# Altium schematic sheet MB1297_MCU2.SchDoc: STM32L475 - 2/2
size A4; DocumentNumber: MB1297; Revision: C; SheetNumber: 3; SheetTotal: 11
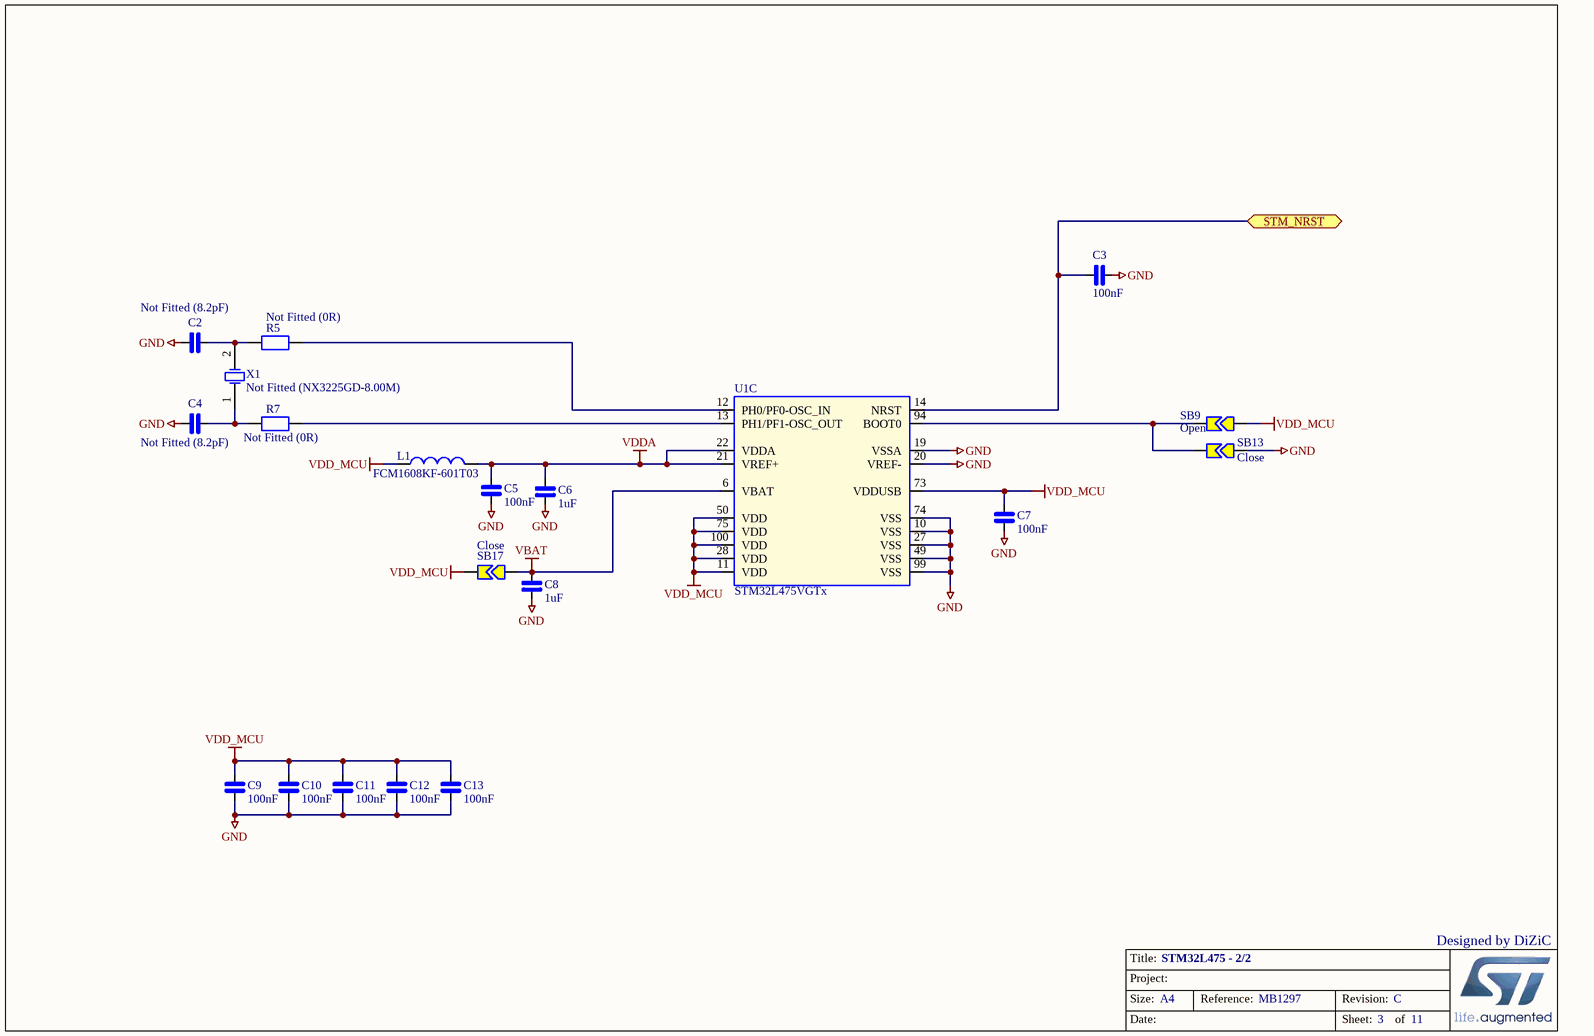
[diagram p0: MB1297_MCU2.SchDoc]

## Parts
C2  Not Fitted (8.2pF)  [0402_CAP_NPOL]
C3  100nF  [0402_CAP_NPOL]
C4  Not Fitted (8.2pF)  [0402_CAP_NPOL]
C5  100nF  [0402_CAP_NPOL]
C6  1uF  [0402_CAP_NPOL]
C7  100nF  [0402_CAP_NPOL]
C8  1uF  [0402_CAP_NPOL]
C9  100nF  [0402_CAP_NPOL]
C10  100nF  [0402_CAP_NPOL]
C11  100nF  [0402_CAP_NPOL]
C12  100nF  [0402_CAP_NPOL]
C13  100nF  [0402_CAP_NPOL]
L1  FCM1608KF-601T03  [0603L]
R5  Not Fitted (0R)  [0402_RES]
R7  Not Fitted (0R)  [0402_RES]
SB9  Open  [SB]
SB13  Close  [SB]
SB17  Close  [SB]
U1  STM32L475VGTx  [LQFP100 14x14x1.6]  (part C of 3)
X1  Not Fitted (NX3225GD-8.00M)  [CRY_NX3225GD_2P]

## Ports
STM_NRST

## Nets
GND: C2.2 C3.1 C4.2 C5.2 C6.1 C7.2 C8.1 C9.2 C10.2 C11.2 C12.2 C13.2 SB13.1 U1.10(VSS) U1.19(VSSA) U1.20(VREF-) U1.27(VSS) U1.49(VSS) U1.74(VSS) U1.99(VSS)
VBAT: C8.2 SB17.2 U1.6(VBAT)
VDD_MCU: C7.1 C9.1 C10.1 C11.1 C12.1 C13.1 L1.1 SB9.1 SB17.1 U1.11(VDD) U1.28(VDD) U1.50(VDD) U1.73(VDDUSB) U1.75(VDD) U1.100(VDD)
VDDA: C5.1 C6.2 L1.2 U1.21(VREF+) U1.22(VDDA)
STM_NRST: C3.2 U1.14(NRST) ; port STM_NRST
NetC2_1: C2.1 R5.2 X1.2(OSC2)
NetC4_1: C4.1 R7.2 X1.1(OSC1)
NetR5_1: R5.1 U1.12(PH0/PF0-OSC_IN)
NetR7_1: R7.1 U1.13(PH1/PF1-OSC_OUT)
NetSB9_2: SB9.2 SB13.2 U1.94(BOOT0)

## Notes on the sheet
- Designed by DiZiC

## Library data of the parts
C2-C13 = CAP_NPOL: Capacitor_not polarized
L1 = Inductor: Value: 100uH
R5 R7 = RES: Resistor; FITTED: NO
SB9 SB13 SB17 = Strap2: Solder Jumper; Solder: YES
X1 = XTAL_8M_NX3225GD: Crystal 8Mhz, 8pF, -+50PPM, SMD; Manuf_1: NDK; Manuf_Part_1: NX3225GD 8MHz EXS00A-CG04874; ECCN_US/EU: EAR99/NEC; NDK Ref: X3127326; Ref St: 9157029; Fitted: NO; Ordered_By: STM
